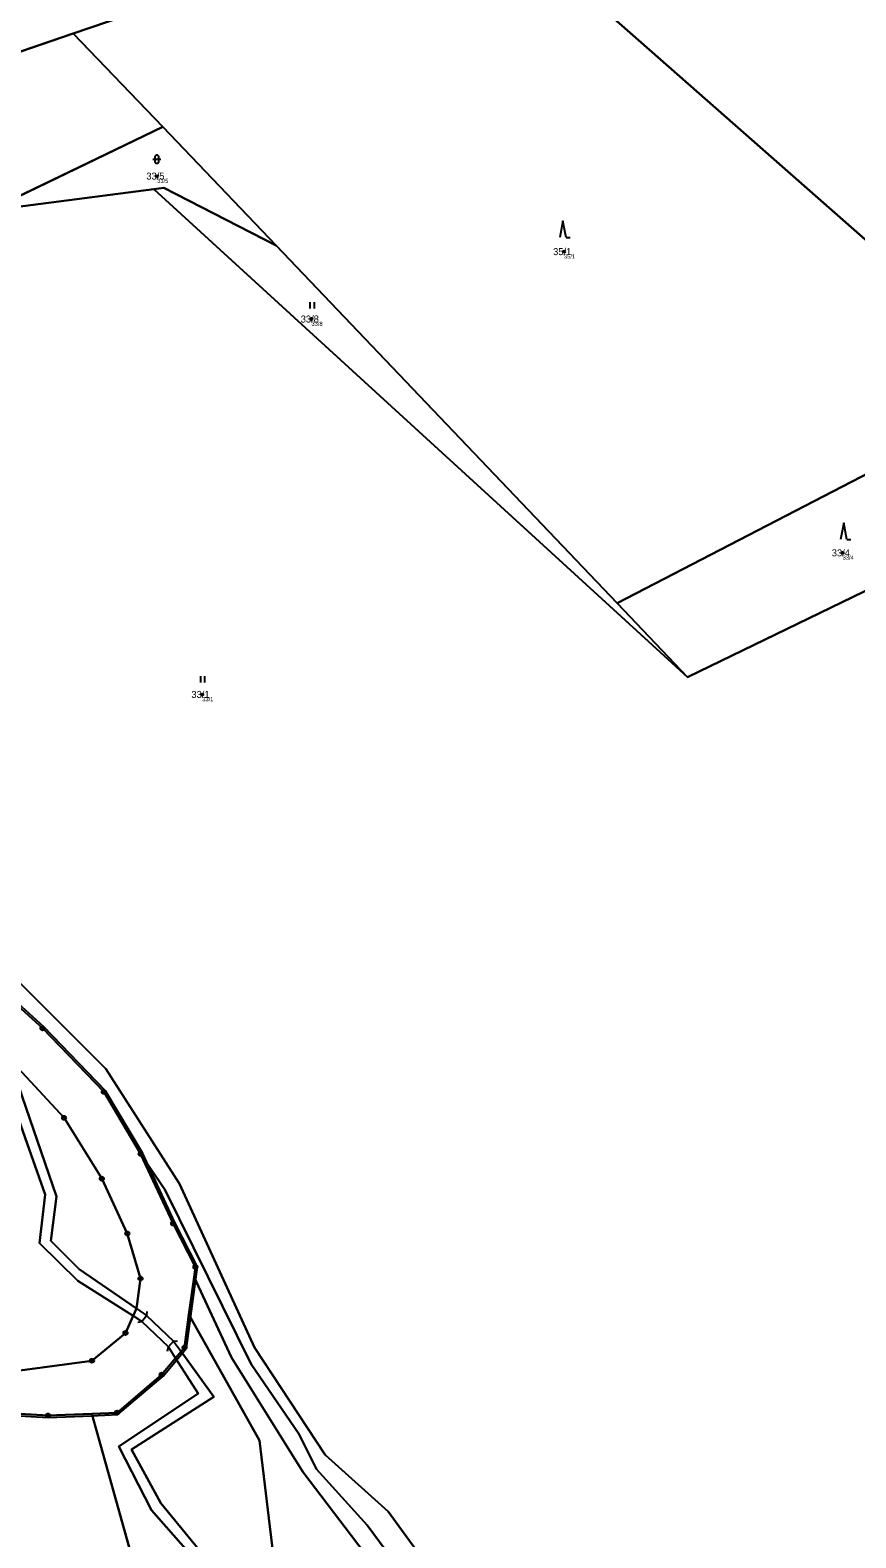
# Model space of a CAD drawing. Extents: x -554500 to -548272, y -1079733 to -1073730.
# Drawn here: x -553289.5 to -553088.8, y -1077731.8 to -1077365.5 of the extents above; entities that cross this region are included whole.
import ezdxf

# ---------------------------------------------------------------- set-up
doc = ezdxf.new("R2010")
doc.units = 0
for name, color, linetype in [('Definiční body', 7, 'Continuous'), ('Hranice parcel', 7, 'Continuous'), ('Parcelní čísla', 7, 'Continuous'), ('Polygon parcely', 7, 'Continuous'), ('Vnitřní kresba', 7, 'Continuous'), ('Značky bodu BP', 7, 'Continuous'), ('Značky kultur', 7, 'Continuous')]:
    doc.layers.add(name, color=color, linetype=linetype)

msp = doc.modelspace()

# ---------------------------------------------------------------- linework, layer by layer
at = {"layer": 'Definiční body'}
for centre in [(-553258.61, -1077400.98994), (-553159.75, -1077419.33994), (-553221.1, -1077435.70994), (-553092.04, -1077492.51994), (-553247.66, -1077526.89994)]:
    msp.add_circle(centre, 0.25, dxfattribs=at)
at = {"layer": 'Hranice parcel'}
for p, q in [((-553181.25, -1077333.07), (-553279.01, -1077366.33)), ((-553071.21, -1077429.91), (-553181.25, -1077333.07)), ((-553279.01, -1077366.33), (-553354.06, -1077392.08)), ((-553257.28, -1077389.01), (-553279.01, -1077366.33)), ((-553257.28, -1077389.01), (-553299.47, -1077409.37)), ((-553229.74, -1077417.88), (-553257.28, -1077389.01)), ((-553259.47, -1077404.13), (-553299.47, -1077409.37)), ((-553129.73, -1077522.73), (-553259.47, -1077404.13)), ((-553146.87, -1077504.73), (-553229.74, -1077417.88)), ((-553057.96, -1077458.75), (-553146.87, -1077504.73)), ((-553146.87, -1077504.73), (-553129.73, -1077522.73)), ((-553249.67, -1077668.47), (-553250.9, -1077677.55)), ((-553263.63, -1077676.06), (-553264.45, -1077677.86)), ((-553254.16, -1077688.13), (-553252.83, -1077686.55)), ((-553274.5, -1077701.63), (-553250.47, -1077787.67))]:
    msp.add_line(p, q, dxfattribs=at)
for points in [[(-553504.52, -1077388.35), (-553497.17, -1077402.92), (-553477.79, -1077440.54), (-553466.46, -1077456.89), (-553452.61, -1077475.58), (-553435.28, -1077492.48), (-553369.57, -1077542.35), (-553331.17, -1077571.81), (-553305.57, -1077590.74), (-553286.49, -1077608.01), (-553271.59, -1077623.45), (-553262.65, -1077638.5)], [(-553124.67, -1077826.32), (-553166.87, -1077774.4), (-553202.51, -1077725.36), (-553217.79, -1077711.63), (-553234.94, -1077685.53), (-553253.23, -1077645.77), (-553271.1, -1077617.89), (-553292.24, -1077596.74), (-553312.52, -1077581.47), (-553347.31, -1077550.23), (-553370.01, -1077535.01), (-553404.4, -1077505.48), (-553427.19, -1077489.13), (-553438.69, -1077476), (-553466.11, -1077437.96), (-553494.38, -1077400.51)], [(-553259.47, -1077404.13), (-553257.02, -1077403.81), (-553229.74, -1077417.88)], [(-553536.81, -1077412.1), (-553527.55, -1077419.96), (-553529.68, -1077432.94), (-553520.8, -1077448.07), (-553513.57, -1077452.73), (-553504.88, -1077469.21), (-553505.15, -1077480.87), (-553493.73, -1077506.61), (-553481.98, -1077516.76), (-553476.08, -1077514.54), (-553465.14, -1077526.37), (-553450.89, -1077533.72), (-553427.61, -1077542.14), (-553406.84, -1077543.71), (-553368.99, -1077557.78), (-553349.01, -1077608.78), (-553314.26, -1077602.65), (-553293.27, -1077619.12), (-553283.07, -1077648.85), (-553284.43, -1077659.67), (-553277.6, -1077666.48), (-553263.63, -1077676.06)], [(-553033.85, -1077498.36), (-553065.44, -1077491.56), (-553129.73, -1077522.73)], [(-553263.63, -1077676.06), (-553262.68, -1077668.79), (-553265.88, -1077657.85), (-553272.08, -1077644.52), (-553281.24, -1077629.75), (-553293.45, -1077616.57), (-553314, -1077600.23), (-553339.02, -1077579.27), (-553374.87, -1077551.62)], [(-553264.45, -1077677.86), (-553277.94, -1077669.33), (-553287.24, -1077660.23), (-553285.83, -1077648.39), (-553295.67, -1077620.59)], [(-553249.67, -1077668.47), (-553249.33, -1077666), (-553254.76, -1077655.42), (-553262.65, -1077638.5)], [(-553262.65, -1077638.5), (-553256.77, -1077647.2), (-553235.79, -1077689.59), (-553224.23, -1077706.53), (-553219.94, -1077715.08), (-553207.6, -1077728.69), (-553167.14, -1077783.3), (-553148.19, -1077803.22), (-553141.14, -1077820.29), (-553103.33, -1077850.71), (-553070.97, -1077897.33)], [(-553144.28, -1077821.04), (-553151.39, -1077804.84), (-553169.79, -1077785.99), (-553223.2, -1077715.78), (-553240.54, -1077687.99), (-553249.67, -1077668.47)], [(-553292.03, -1077691.16), (-553274.46, -1077688.76), (-553266.33, -1077682.02), (-553264.45, -1077677.86)], [(-553250.9, -1077677.55), (-553251.98, -1077685.54), (-553252.83, -1077686.55)], [(-553250.9, -1077677.55), (-553233.76, -1077708.1), (-553228.43, -1077752.59), (-553212.42, -1077768.32), (-553195.21, -1077777.52), (-553178.42, -1077802.4), (-553165.78, -1077817.79), (-553153.24, -1077822.66), (-553144.28, -1077821.04)], [(-553254.16, -1077688.13), (-553257.53, -1077692.15), (-553268.36, -1077701.38), (-553274.5, -1077701.63)], [(-553106.75, -1077916.51), (-553107.4, -1077902.63), (-553125.69, -1077874.99), (-553141.08, -1077866.15), (-553173.88, -1077834.88), (-553170.89, -1077820.22), (-553205.23, -1077778.53), (-553239.85, -1077777.82), (-553251.07, -1077735.14), (-553260.04, -1077725.07), (-553267.92, -1077709.59), (-553248.65, -1077696.73), (-553254.16, -1077688.13)], [(-553252.83, -1077686.55), (-553244.83, -1077697.51), (-553264.85, -1077710.32), (-553257.72, -1077723.32), (-553248.53, -1077734.63), (-553237.72, -1077775.59), (-553204.6, -1077776.45), (-553168.43, -1077819.04), (-553171.49, -1077833.97), (-553139.32, -1077864.66), (-553124.05, -1077873.23), (-553104.95, -1077901.73), (-553104.46, -1077915.64), (-553071.4, -1077935.4), (-553063.82, -1077954.33), (-553052.7, -1077958.22)], [(-553274.5, -1077701.63), (-553285.13, -1077702.06), (-553307.42, -1077700.75)]]:
    msp.add_lwpolyline(points, dxfattribs=at)
at = {"layer": 'Polygon parcely'}
for points in [[(-553356.85, -1077361), (-553268.86, -1077335.82), (-553199.68, -1077316.65), (-553181.25, -1077333.07), (-553071.21, -1077429.91), (-553029.53, -1077390.07), (-553042.91, -1077386.27), (-553043.22, -1077375.67), (-553053.92, -1077365.88), (-553057.31, -1077362.66), (-553072.49, -1077352.41), (-553132.3, -1077313.83), (-553140.36, -1077310.43), (-553150.74, -1077306.06), (-553198.71, -1077285.9), (-553217.36, -1077265.84), (-553227.76, -1077257.51), (-553265.09, -1077203.57), (-553271.71, -1077195.05), (-553294.48, -1077166.28)], [(-552947.3, -1077742.02), (-552957.02, -1077703.28), (-552824.32, -1077661.59), (-552868.83, -1077577.65), (-552926.2, -1077594.96), (-552982.83, -1077615.51), (-552996.86, -1077584.1), (-553033.85, -1077498.36), (-553065.44, -1077491.56), (-553129.73, -1077522.73), (-553259.47, -1077404.13), (-553299.47, -1077409.37)], [(-553307.42, -1077700.75), (-553285.13, -1077702.06), (-553274.5, -1077701.63), (-553268.36, -1077701.38), (-553257.53, -1077692.15), (-553254.16, -1077688.13), (-553252.83, -1077686.55), (-553251.98, -1077685.54), (-553250.9, -1077677.55), (-553249.67, -1077668.47), (-553249.33, -1077666), (-553254.76, -1077655.42), (-553262.65, -1077638.5), (-553271.59, -1077623.45), (-553286.49, -1077608.01), (-553305.57, -1077590.74)], [(-553305.57, -1077590.74), (-553286.49, -1077608.01), (-553271.59, -1077623.45), (-553262.65, -1077638.5), (-553256.77, -1077647.2), (-553235.79, -1077689.59), (-553224.23, -1077706.53), (-553219.94, -1077715.08), (-553207.6, -1077728.69), (-553167.14, -1077783.3)], [(-553166.87, -1077774.4), (-553202.51, -1077725.36), (-553217.79, -1077711.63), (-553234.94, -1077685.53), (-553253.23, -1077645.77), (-553271.1, -1077617.89), (-553292.24, -1077596.74)], [(-553292.24, -1077596.74), (-553271.1, -1077617.89), (-553253.23, -1077645.77), (-553234.94, -1077685.53), (-553217.79, -1077711.63), (-553202.51, -1077725.36), (-553166.87, -1077774.4)], [(-553293.45, -1077616.57), (-553281.24, -1077629.75), (-553272.08, -1077644.52), (-553265.88, -1077657.85), (-553262.68, -1077668.79), (-553263.63, -1077676.06), (-553264.45, -1077677.86), (-553266.33, -1077682.02), (-553274.46, -1077688.76), (-553292.03, -1077691.16)], [(-553293.27, -1077619.12), (-553283.07, -1077648.85), (-553284.43, -1077659.67), (-553277.6, -1077666.48), (-553263.63, -1077676.06), (-553262.68, -1077668.79), (-553265.88, -1077657.85), (-553272.08, -1077644.52), (-553281.24, -1077629.75), (-553293.45, -1077616.57)], [(-553295.67, -1077620.59), (-553285.83, -1077648.39), (-553287.24, -1077660.23), (-553277.94, -1077669.33), (-553264.45, -1077677.86), (-553263.63, -1077676.06), (-553277.6, -1077666.48), (-553284.43, -1077659.67), (-553283.07, -1077648.85), (-553293.27, -1077619.12)], [(-553292.03, -1077691.16), (-553274.46, -1077688.76), (-553266.33, -1077682.02), (-553264.45, -1077677.86), (-553277.94, -1077669.33), (-553287.24, -1077660.23), (-553285.83, -1077648.39), (-553295.67, -1077620.59)], [(-553167.14, -1077783.3), (-553207.6, -1077728.69), (-553219.94, -1077715.08), (-553224.23, -1077706.53), (-553235.79, -1077689.59), (-553256.77, -1077647.2), (-553262.65, -1077638.5), (-553254.76, -1077655.42), (-553249.33, -1077666), (-553249.67, -1077668.47), (-553240.54, -1077687.99), (-553223.2, -1077715.78), (-553169.79, -1077785.99)], [(-553228.43, -1077752.59), (-553233.76, -1077708.1), (-553250.9, -1077677.55), (-553251.98, -1077685.54), (-553252.83, -1077686.55), (-553244.83, -1077697.51), (-553264.85, -1077710.32), (-553257.72, -1077723.32), (-553248.53, -1077734.63)], [(-553248.53, -1077734.63), (-553257.72, -1077723.32), (-553264.85, -1077710.32), (-553244.83, -1077697.51), (-553252.83, -1077686.55), (-553254.16, -1077688.13), (-553248.65, -1077696.73), (-553267.92, -1077709.59), (-553260.04, -1077725.07), (-553251.07, -1077735.14)]]:
    msp.add_lwpolyline(points, dxfattribs=at)
for points in [[(-553500.22, -1077248.33), (-553530.61, -1077244.06), (-553537.4, -1077247.89), (-553499.14, -1077250.48), (-553427.96, -1077322.54), (-553406.19, -1077354.83), (-553361.2, -1077394.46), (-553354.06, -1077392.08), (-553279.01, -1077366.33), (-553181.25, -1077333.07), (-553199.68, -1077316.65), (-553268.86, -1077335.82), (-553366.23, -1077365.2), (-553368.96, -1077365.98), (-553400.19, -1077347.66), (-553410.95, -1077332.11), (-553408.98, -1077323.1), (-553443.63, -1077280.81), (-553464.79, -1077262.64)], [(-553181.25, -1077333.07), (-553279.01, -1077366.33), (-553257.28, -1077389.01), (-553229.74, -1077417.88), (-553146.87, -1077504.73), (-553057.96, -1077458.75), (-553077.02, -1077435.42), (-553071.21, -1077429.91)], [(-553279.01, -1077366.33), (-553354.06, -1077392.08), (-553336.53, -1077414.65), (-553313.02, -1077411.15), (-553299.47, -1077409.37), (-553257.28, -1077389.01)], [(-553299.47, -1077409.37), (-553259.47, -1077404.13), (-553257.02, -1077403.81), (-553229.74, -1077417.88), (-553257.28, -1077389.01)], [(-553229.74, -1077417.88), (-553257.02, -1077403.81), (-553259.47, -1077404.13), (-553129.73, -1077522.73), (-553146.87, -1077504.73)], [(-553057.96, -1077458.75), (-553146.87, -1077504.73), (-553129.73, -1077522.73), (-553065.44, -1077491.56), (-553033.85, -1077498.36), (-553052.64, -1077465.27)], [(-553144.28, -1077821.04), (-553151.39, -1077804.84), (-553169.79, -1077785.99), (-553223.2, -1077715.78), (-553240.54, -1077687.99), (-553249.67, -1077668.47), (-553250.9, -1077677.55), (-553233.76, -1077708.1), (-553228.43, -1077752.59), (-553212.42, -1077768.32), (-553195.21, -1077777.52), (-553178.42, -1077802.4), (-553165.78, -1077817.79), (-553153.24, -1077822.66)], [(-553431.6, -1077678.14), (-553449.37, -1077676.98), (-553474.82, -1077687.92), (-553471.27, -1077810.47), (-553400.22, -1077830.02), (-553336.14, -1077877.78), (-553250.47, -1077787.67), (-553274.5, -1077701.63), (-553285.13, -1077702.06), (-553307.42, -1077700.75), (-553362.87, -1077724.21), (-553397.84, -1077683.51)], [(-553274.5, -1077701.63), (-553250.47, -1077787.67), (-553180.01, -1077884.21), (-553165.36, -1077901.86), (-553106.75, -1077916.51), (-553107.4, -1077902.63), (-553125.69, -1077874.99), (-553141.08, -1077866.15), (-553173.88, -1077834.88), (-553170.89, -1077820.22), (-553205.23, -1077778.53), (-553239.85, -1077777.82), (-553251.07, -1077735.14), (-553260.04, -1077725.07), (-553267.92, -1077709.59), (-553248.65, -1077696.73), (-553254.16, -1077688.13), (-553257.53, -1077692.15), (-553268.36, -1077701.38)]]:
    msp.add_lwpolyline(points, close=True, dxfattribs=at)
at = {"layer": 'Vnitřní kresba'}
for p, q in [((-553286.13, -1077607.66), (-553305.23, -1077590.37)), ((-553271.16, -1077623.19), (-553286.13, -1077607.66)), ((-553262.2, -1077638.29), (-553271.16, -1077623.19)), ((-553254.31, -1077655.19), (-553262.2, -1077638.29)), ((-553248.85, -1077665.91), (-553254.31, -1077655.19)), ((-553251.53, -1077685.74), (-553248.85, -1077665.91)), ((-553262.37, -1077679.2), (-553264.45, -1077677.86)), ((-553263.63, -1077676.06), (-553261.18, -1077677.78)), ((-553262.37, -1077679.2), (-553261.18, -1077677.78)), ((-553261.18, -1077677.78), (-553254.67, -1077684.03)), ((-553261.11, -1077676.782), (-553261.179, -1077677.779)), ((-553263.345, -1077679.424), (-553262.371, -1077679.2)), ((-553262.37, -1077679.2), (-553255.89, -1077685.42)), ((-553257.15, -1077692.47), (-553251.53, -1077685.74)), ((-553256.081, -1077686.402), (-553255.891, -1077685.42)), ((-553255.89, -1077685.42), (-553254.67, -1077684.03)), ((-553254.16, -1077688.13), (-553255.89, -1077685.42)), ((-553254.67, -1077684.03), (-553252.83, -1077686.55)), ((-553253.67, -1077684.065), (-553254.669, -1077684.031)), ((-553268.18, -1077701.84), (-553257.15, -1077692.47)), ((-553307.49, -1077701.24), (-553285.13, -1077702.56)), ((-553285.13, -1077702.56), (-553274.48, -1077702.13)), ((-553274.48, -1077702.13), (-553268.18, -1077701.84))]:
    msp.add_line(p, q, dxfattribs=at)
at = {"layer": 'Značky bodu BP'}
for centre, radius in [((-553286.49, -1077608.00988), 0.5), ((-553286.49, -1077608.00988), 0.0303), ((-553271.59, -1077623.44988), 0.5), ((-553271.59, -1077623.44988), 0.0303), ((-553281.24, -1077629.74988), 0.5), ((-553281.24, -1077629.74988), 0.0303), ((-553262.65, -1077638.49988), 0.5), ((-553262.65, -1077638.49988), 0.0303), ((-553272.08, -1077644.51988), 0.5), ((-553272.08, -1077644.51988), 0.0303), ((-553254.76, -1077655.41988), 0.5), ((-553254.76, -1077655.41988), 0.0303), ((-553265.88, -1077657.84988), 0.5), ((-553265.88, -1077657.84988), 0.0303), ((-553249.33, -1077665.99988), 0.5), ((-553249.33, -1077665.99988), 0.0303), ((-553262.68, -1077668.78988), 0.5), ((-553262.68, -1077668.78988), 0.0303), ((-553266.33, -1077682.01988), 0.5), ((-553266.33, -1077682.01988), 0.0303), ((-553251.98, -1077685.53988), 0.5), ((-553251.98, -1077685.53988), 0.0303), ((-553274.46, -1077688.75988), 0.5), ((-553274.46, -1077688.75988), 0.0303), ((-553257.53, -1077692.14988), 0.5), ((-553257.53, -1077692.14988), 0.0303), ((-553268.36, -1077701.37988), 0.5), ((-553285.13, -1077702.05988), 0.5), ((-553285.13, -1077702.05988), 0.0303), ((-553268.36, -1077701.37988), 0.0303)]:
    msp.add_circle(centre, radius, dxfattribs=at)
at = {"layer": 'Značky kultur'}
for p, q in [((-553259.701, -1077396.891), (-553257.699, -1077396.891)), ((-553259.201, -1077396.391), (-553259.201, -1077397.392)), ((-553258.199, -1077397.392), (-553258.199, -1077396.391)), ((-553160.01, -1077411.89), (-553160.76, -1077415.89)), ((-553159.26, -1077415.89), (-553160.01, -1077411.89)), ((-553159.26, -1077415.89), (-553158.264, -1077415.89)), ((-553221.421, -1077433.13), (-553221.421, -1077431.63)), ((-553220.42, -1077433.13), (-553220.42, -1077431.63)), ((-553091.79, -1077485.24), (-553092.54, -1077489.24)), ((-553091.04, -1077489.24), (-553091.79, -1077485.24)), ((-553091.04, -1077489.24), (-553090.044, -1077489.24)), ((-553248.021, -1077523.99), (-553248.021, -1077522.49)), ((-553247.02, -1077523.99), (-553247.02, -1077522.49))]:
    msp.add_line(p, q, dxfattribs=at)
for centre, start, end in [((-553258.7, -1077396.3909), 0, 180), ((-553258.7, -1077397.3909), 180, 359.9878861)]:
    msp.add_arc(centre, 0.5, start, end, dxfattribs=at)

# ---------------------------------------------------------------- texts
at = {"layer": 'Definiční body'}
for s, p in [('33/5', (-553258.61, -1077402.646)), ('35/1', (-553159.75, -1077420.996)), ('33/8', (-553221.1, -1077437.366)), ('33/4', (-553092.04, -1077494.176)), ('33/1', (-553247.66, -1077528.556))]:
    msp.add_text(s, height=0.999996, dxfattribs=at).set_placement(p)
at = {"layer": 'Parcelní čísla'}
for s, p in [('33/5', (-553261.259, -1077401.84)), ('35/1', (-553162.399, -1077420.19)), ('33/8', (-553223.749, -1077436.56)), ('33/4', (-553094.689, -1077493.37)), ('33/1', (-553250.309, -1077527.75))]:
    msp.add_text(s, height=1.699998, dxfattribs=at).set_placement(p)

doc.saveas('drawing.dxf')
